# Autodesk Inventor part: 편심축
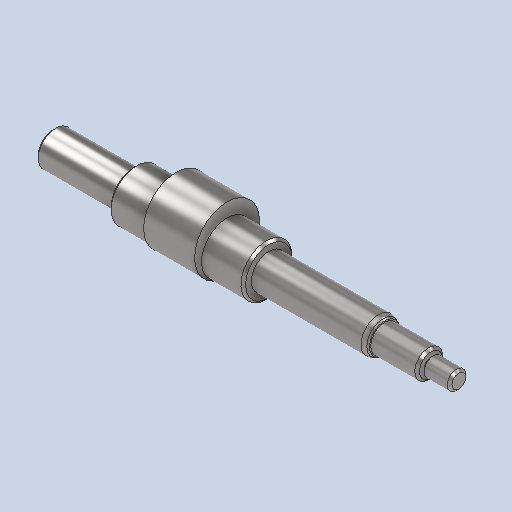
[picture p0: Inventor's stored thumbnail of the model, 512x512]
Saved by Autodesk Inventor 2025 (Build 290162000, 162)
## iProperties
Created: 2025-08
Part Number: 편심축
Material: 강철, 연강
Document SubType Name: Modeling
Designer: infra02
Density: 7.86 g/cm^3
Appearance: 기본값
Author: jhkim
Sending System: Autodesk Inventor 2026
Preprocessor: ST-DEVELOPER v20.1
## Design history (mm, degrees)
feature "솔리드1"
node "솔리드2"
